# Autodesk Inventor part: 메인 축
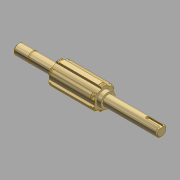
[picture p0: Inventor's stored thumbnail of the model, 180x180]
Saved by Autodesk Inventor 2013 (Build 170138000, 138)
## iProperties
Created: 2015-11
Part Number: 메인 축
Document SubType Name: 모델링
Designer: mdu
Mass: 21.4462 g
Surface Area: 72.5109 cm^2
Volume: 21.4462 cm^3
Density: 1 g/cm^3
Material: 일반
변환 표준: STEP AP214IS
파일 이름: C:\Users\SeoGD\Desktop\?쒗뿕\硫붿씤 異?.stp
전처리기: Build: 253, Release: 2010 SP1 - Date: Wed 07/29/2009
전송 단위: 밀리미터
불확실성: 0.01
Author: mdu
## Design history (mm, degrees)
sketch "스케치1"
  geometry: L1 (-69.5, 0)-(69.5, 0); L2 (69.5, 0)-(69.5, 5); L3 (69.5, 5)-(55.5, 5); L4 (55.5, 5)-(55.5, 4.8); L5 (55.5, 4.8)-(54.35, 4.8); L6 (54.35, 4.8)-(54.35, 5); L7 (54.35, 5)-(30.5, 5); L8 (30.5, 5)-(30.5, 9); L9 (30.5, 9)-(-13.5, 9); L10 (-13.5, 9)-(-13.5, 7); L11 (-13.5, 7)-(-17.5, 7); L12 (-17.5, 7)-(-17.5, 5); L13 (-17.5, 5)-(-69.5, 5); L14 (-69.5, 5)-(-69.5, 0); 2 further points
  constraints: 28 end point, 9 parallel, 4 collinear, 2 perpendicular, 1 coincident, 1 horizontal, 1 midpoint
  dimensions: "d2" = 1.15 distance between parallel lines of L6 L4; "d3" = 10 diameter of L3 L1; "d4" = 9.6 diameter of L5 L1; "d6" = 44 distance between parallel lines of L10 L8; "d7" = 4 distance between parallel lines of L12 L10; "d8" = 14 diameter of L11 L1; "d9" = 18 diameter of L9 L1; "d33" = 52 distance from line of L12.end L14; "d37" = 39 distance between parallel lines of L8 L2; "d38" = 14 distance between parallel lines of L2 L4
revolve "회전1" sketch "스케치1" stored, may be unused: angle "d10" = 90 deg
sketch "스케치2"
  geometry: L1 (2.5, 10.712)-(2.5, 8.646); L2 (-2.5, 10.712)-(-2.5, 8.646); A1 r 9 centre (0, 0) between (2.5, 8.646) and (-2.5, 8.646) reference; A2 r 11 centre (0, 0) between (2.5, 10.712) and (-2.5, 10.712); 1 further point
  constraints: 4 end point, 4 point on circle, 2 parallel, 1 centre point, 1 coincident, 1 vertical
  dimensions: "d11" = 22 diameter of A2; "d12" = 5 distance between parallel lines of L1 L2
extrude "돌출1" join sketch "스케치2" stored distance "d13" = 10; taper "d14" = 0 deg
chamfer "모따기1" distance "d15" = 1; stored, may be unused: second distance "d16" = 2, angle "d17" = 45 deg
node "작업 평면1"
node "작업 평면2"
sketch "스케치3"
  geometry: L1 (2.5, 10.712)-(2.5, 10.198); L2 (-2.5, 10.712)-(-2.5, 10.198); A1 r 11 centre (0, 0) between (2.5, 10.712) and (-2.5, 10.712) reference; A2 r 10.5 centre (0, 0) between (2.5, 10.198) and (-2.5, 10.198); 1 further point
  constraints: 4 end point, 2 point on circle, 1 centre point, 1 coincident, 1 parallel, 1 vertical
  dimensions: "d19" = 21 diameter of A2
extrude "돌출2" cut sketch "스케치3" distance "d20" = 1.35; taper "d21" = 0 deg
node "작업 평면3"
sketch "스케치4"
  geometry: L1 (-26, -5)-(-26, 5) reference; L2 (-26, 1.5)-(-12.5, 1.5); L3 (-12.5, -1.5)-(-26, -1.5); A1 r 1.5 centre (-12.5, 0) between (-12.5, -1.5) and (-12.5, 1.5); 2 further points
  constraints: 4 end point, 2 perpendicular, 2 point on circle, 2 point on line, 2 tangent, 1 centre point, 1 horizontal alignment, 1 midpoint
  dimensions: "d25" = 3 distance between parallel lines of L3 L2; "d26" = 15 dimension on A1 L1
extrude "돌출3" cut sketch "스케치4" distance "d27" = 1.8; taper "d28" = 0 deg
chamfer "모따기2" distance "d29" = 1; stored, may be unused: second distance "d30" = 2, angle "d31" = 45 deg
node "솔리드1"
node "솔리드 본체"
node "곡면 본체"
mirror "대칭1"
pattern_circular "원형 패턴1" dims "d23" = 360 deg
node "솔리드2"
other parameters: "d18" = -1.65
